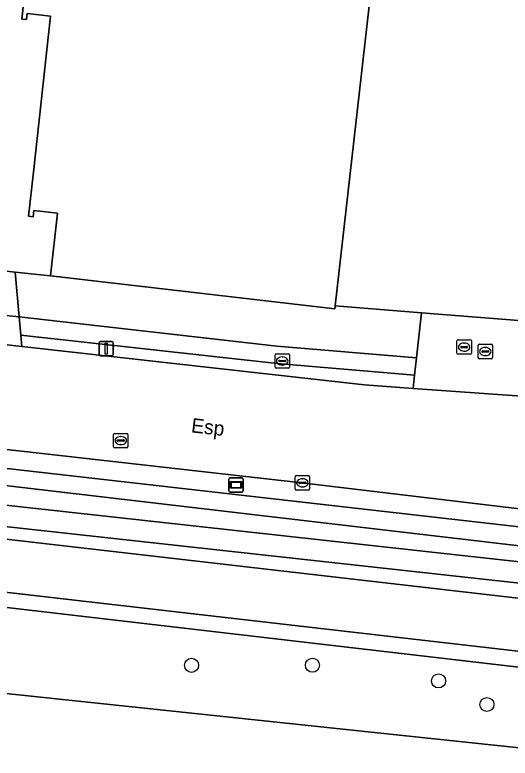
# Model space of a CAD drawing. Extents: x 161385 to 162589, y 388479 to 389756.
# Drawn here: x 162384.5 to 162418.9, y 388644.4 to 388696.1 of the extents above; entities that cross this region are included whole.
import ezdxf

# ---------------------------------------------------------------- set-up
doc = ezdxf.new("R2010")
doc.units = 0
for name, color, linetype in [('IMGEO_Berm_groen', 7, 'Continuous'), ('IMGEO_Boom', 7, 'Continuous'), ('IMGEO_Brandkraan', 7, 'Continuous'), ('IMGEO_Erf', 7, 'Continuous'), ('IMGEO_Fietspad_gesloten', 7, 'Continuous'), ('IMGEO_Gemengd_bos', 7, 'Continuous'), ('IMGEO_Groenvoorziening', 7, 'Continuous'), ('IMGEO_Haag', 7, 'Continuous'), ('IMGEO_Hek', 7, 'Continuous'), ('IMGEO_Kolk', 7, 'Continuous'), ('IMGEO_Lichtmast', 7, 'Continuous'), ('IMGEO_Oever', 7, 'Continuous'), ('IMGEO_Openbare_ruimte_label', 7, 'Continuous'), ('IMGEO_Pand', 7, 'Continuous'), ('IMGEO_Rijbaan_lokaal_gesloten', 7, 'Continuous'), ('IMGEO_Rioolput', 7, 'Continuous'), ('IMGEO_Voetpad_open', 7, 'Continuous'), ('IMGEO_Waterloop', 7, 'Continuous'), ('IMGEO_Wegwijzer', 7, 'Continuous')]:
    doc.layers.add(name, color=color, linetype=linetype)

msp = doc.modelspace()

# ---------------------------------------------------------------- linework, layer by layer
at = {"layer": 'IMGEO_Berm_groen'}
msp.add_lwpolyline([(162384.891, 388673.825), (162384.963, 388673.046), (162408.796, 388670.377), (162412.183, 388670.136), (162412.286, 388671.047), (162402.725, 388671.854)], close=True, dxfattribs=at)
for points in [[(162461.096, 388654.743), (162455.305, 388656.124), (162451.142, 388657.117), (162433.533, 388660.124), (162428.321, 388660.721), (162404.449, 388663.572), (162379.371, 388666.385), (162354.354, 388669.216), (162352.961, 388669.418), (162351.555, 388669.495), (162350.951, 388669.489), (162349.541, 388669.386), (162348.146, 388669.157), (162346.778, 388668.804), (162345.446, 388668.33), (162344.161, 388667.74), (162343.323, 388667.275), (162343.185, 388667.161), (162343.057, 388667.034), (162342.942, 388666.897), (162342.839, 388666.75), (162342.749, 388666.595), (162342.711, 388666.516)], [(162353.131, 388667.917), (162357.64, 388667.549), (162433.197, 388658.957), (162436.225, 388658.419), (162436.595, 388658.23), (162437.013, 388657.873), (162437.321, 388657.419), (162437.524, 388656.717), (162437.256, 388654.736)], [(162342.861, 388664.571), (162343.854, 388664.303), (162356.884, 388662.764), (162437.393, 388653.479), (162447.573, 388652.333)], [(162435.304, 388653.875), (162432.217, 388654.406), (162426.956, 388655.776), (162357.235, 388663.453), (162352.368, 388663.746)], [(162444.332, 388649.048), (162443.05, 388649.15), (162347.086, 388660.188)], [(162343.501, 388659.601), (162454.958, 388646.611)]]:
    msp.add_lwpolyline(points, dxfattribs=at)
at = {"layer": 'IMGEO_Boom'}
for centre in [(162396.77, 388650.877), (162405.18, 388650.883), (162413.953, 388649.79), (162417.32, 388648.153)]:
    msp.add_circle(centre, 0.489, dxfattribs=at)
at = {"layer": 'IMGEO_Brandkraan'}
for p, q in [((162402.653, 388672.538), (162403.505, 388672.538)), ((162402.578, 388671.612), (162402.578, 388672.464)), ((162402.837, 388672.032), (162402.837, 388672.044)), ((162403.275, 388671.995), (162402.877, 388671.995)), ((162402.88, 388672.081), (162403.278, 388672.081)), ((162403.066, 388672.318), (162403.091, 388672.318)), ((162403.321, 388672.044), (162403.321, 388672.032)), ((162403.579, 388672.464), (162403.579, 388671.612)), ((162403.505, 388671.538), (162402.653, 388671.538)), ((162403.089, 388671.758), (162403.064, 388671.758))]:
    msp.add_line(p, q, dxfattribs=at)
for points in [[(162402.653, 388672.538), (162403.505, 388672.538)], [(162402.578, 388671.612), (162402.578, 388672.464)], [(162403.579, 388672.464), (162403.579, 388671.612)], [(162403.505, 388671.538), (162402.653, 388671.538)]]:
    msp.add_lwpolyline(points, dxfattribs=at)
for centre, radius, start, end in [((162402.655, 388672.462), 0.0765, 91.552, 178.448), ((162402.655, 388672.462), 0.0765, 91.552, 178.448), ((162403.503, 388672.462), 0.0765, 1.552, 88.448), ((162403.503, 388672.462), 0.0765, 1.552, 88.448), ((162402.877, 388672.041), 0.0403, 85.8775, 175.7526), ((162402.874, 388672.031), 0.0366, 178.938, 274.7102), ((162403.278, 388672.038), 0.043, 264.8664, 352.4533), ((162403.282, 388672.043), 0.0386, 1.7309, 96.639), ((162402.655, 388671.614), 0.0765, 181.552, 268.448), ((162402.655, 388671.614), 0.0765, 181.552, 268.448), ((162403.503, 388671.614), 0.0765, 271.552, 358.448), ((162403.503, 388671.614), 0.0765, 271.552, 358.448)]:
    msp.add_arc(centre, radius, start, end, dxfattribs=at)
for centre, major_axis, ratio, start_param, end_param in [((162403.065, 388672.038), (-0.387, 0.002), 0.722429, 4.712389, 7.853982), ((162403.09, 388672.038), (-0.39, 0.002), 0.717154, 1.570796, 4.712389)]:
    msp.add_ellipse(centre, major_axis=major_axis, ratio=ratio, start_param=start_param, end_param=end_param, dxfattribs=at)
at = {"layer": 'IMGEO_Erf'}
for points in [[(162383.967, 388722.64), (162411.707, 388719.457), (162406.76, 388675.873), (162412.776, 388675.396), (162420.122, 388674.813), (162420.461, 388674.786), (162446.489, 388672.997), (162447.18, 388679), (162448.384, 388678.861), (162448.49, 388679.822), (162449.227, 388686.456), (162448.051, 388686.549), (162448.713, 388692.673), (162448.008, 388692.753), (162425.971, 388695.283), (162429.384, 388725.33), (162435.4, 388724.653), (162435.751, 388727.776), (162406.633, 388731.063), (162412.095, 388778.923)], [(162379.117, 388678.821), (162384.504, 388678.222), (162386.947, 388677.951), (162387.452, 388682.311), (162385.802, 388682.494), (162385.755, 388682.067), (162385.427, 388682.103), (162385.766, 388685.174), (162386.965, 388696.018), (162385.325, 388696.199), (162385.279, 388695.782), (162384.951, 388695.818), (162386.201, 388707.129), (162384.591, 388707.307), (162384.544, 388706.88), (162384.216, 388706.916), (162385.484, 388718.406), (162383.83, 388718.549)], [(162443.528, 388629.496), (162453.713, 388637.19), (162458.56, 388641.004), (162341.543, 388653.38), (162336.168, 388605.315)]]:
    msp.add_lwpolyline(points, dxfattribs=at)
at = {"layer": 'IMGEO_Fietspad_gesloten'}
for points in [[(162447.573, 388652.333), (162437.393, 388653.479), (162356.884, 388662.764)], [(162338.468, 388662.352), (162347.086, 388660.188), (162443.05, 388649.15), (162444.332, 388649.048)]]:
    msp.add_lwpolyline(points, dxfattribs=at)
at = {"layer": 'IMGEO_Gemengd_bos'}
msp.add_lwpolyline([(162341.994, 388657.41), (162341.543, 388653.38), (162458.56, 388641.004), (162459.614, 388641.987), (162460.571, 388643.599), (162460.446, 388643.694), (162457.403, 388645.374), (162454.958, 388646.611), (162343.501, 388659.601)], dxfattribs=at)
at = {"layer": 'IMGEO_Groenvoorziening'}
msp.add_lwpolyline([(162384.504, 388678.222), (162384.771, 388675.111), (162402.707, 388673.075), (162412.421, 388672.249), (162412.776, 388675.396), (162406.76, 388675.873), (162406.736, 388675.658), (162386.947, 388677.951)], close=True, dxfattribs=at)
at = {"layer": 'IMGEO_Haag'}
msp.add_lwpolyline([(162384.504, 388678.222), (162384.771, 388675.111), (162402.707, 388673.075), (162412.421, 388672.249), (162412.776, 388675.396), (162406.76, 388675.873), (162406.736, 388675.658), (162386.947, 388677.951)], close=True, dxfattribs=at)
at = {"layer": 'IMGEO_Hek'}
for points in [[(162412.776, 388675.396), (162406.76, 388675.873)], [(162420.122, 388674.813), (162412.776, 388675.396)]]:
    msp.add_lwpolyline(points, dxfattribs=at)
at = {"layer": 'IMGEO_Kolk'}
for p, q in [((162403.981, 388663.141), (162403.981, 388663.993)), ((162404.056, 388664.067), (162404.908, 388664.067)), ((162404.469, 388663.847), (162404.494, 388663.847)), ((162404.982, 388663.993), (162404.982, 388663.141)), ((162404.24, 388663.561), (162404.24, 388663.573)), ((162404.678, 388663.524), (162404.28, 388663.524)), ((162404.283, 388663.61), (162404.681, 388663.61)), ((162404.492, 388663.287), (162404.467, 388663.287)), ((162404.724, 388663.573), (162404.724, 388663.561)), ((162404.908, 388663.067), (162404.056, 388663.067))]:
    msp.add_line(p, q, dxfattribs=at)
for points in [[(162403.981, 388663.141), (162403.981, 388663.993)], [(162404.056, 388664.067), (162404.908, 388664.067)], [(162404.982, 388663.993), (162404.982, 388663.141)], [(162404.908, 388663.067), (162404.056, 388663.067)]]:
    msp.add_lwpolyline(points, dxfattribs=at)
for centre, radius, start, end in [((162404.058, 388663.991), 0.0765, 91.552, 178.448), ((162404.058, 388663.991), 0.0765, 91.552, 178.448), ((162404.906, 388663.991), 0.0765, 1.552, 88.448), ((162404.906, 388663.991), 0.0765, 1.552, 88.448), ((162404.28, 388663.57), 0.0403, 85.8775, 175.7526), ((162404.277, 388663.56), 0.0366, 178.938, 274.7102), ((162404.681, 388663.567), 0.043, 264.8664, 352.4533), ((162404.685, 388663.572), 0.0386, 1.7309, 96.639), ((162404.058, 388663.143), 0.0765, 181.552, 268.448), ((162404.058, 388663.143), 0.0765, 181.552, 268.448), ((162404.906, 388663.143), 0.0765, 271.552, 358.448), ((162404.906, 388663.143), 0.0765, 271.552, 358.448)]:
    msp.add_arc(centre, radius, start, end, dxfattribs=at)
for centre, major_axis, ratio, start_param, end_param in [((162404.468, 388663.567), (-0.387, 0.002), 0.722429, 4.712389, 7.853982), ((162404.493, 388663.567), (-0.39, 0.002), 0.717154, 1.570796, 4.712389)]:
    msp.add_ellipse(centre, major_axis=major_axis, ratio=ratio, start_param=start_param, end_param=end_param, dxfattribs=at)
at = {"layer": 'IMGEO_Lichtmast'}
for p, q in [((162390.335, 388672.501), (162390.335, 388673.301)), ((162390.335, 388673.301), (162390.335, 388672.501)), ((162390.435, 388673.401), (162391.225, 388673.401)), ((162391.225, 388673.401), (162390.435, 388673.401)), ((162391.325, 388673.301), (162391.325, 388672.501)), ((162391.325, 388672.501), (162391.325, 388673.301)), ((162391.225, 388672.401), (162390.435, 388672.401)), ((162390.435, 388672.401), (162391.225, 388672.401))]:
    msp.add_line(p, q, dxfattribs=at)
msp.add_lwpolyline([(162390.755, 388673.276), (162390.905, 388673.276), (162390.905, 388672.526), (162390.755, 388672.526), (162390.755, 388673.276)], dxfattribs=at)
for centre, start, end in [((162390.435, 388673.301), 90, 180), ((162390.435, 388673.301), 90, 180), ((162391.225, 388673.301), 0, 90), ((162391.225, 388673.301), 360, 90), ((162390.435, 388672.501), 180, 270), ((162390.435, 388672.501), 180, 270), ((162391.225, 388672.501), 270, 0), ((162391.225, 388672.501), 270, 0)]:
    msp.add_arc(centre, 0.1, start, end, dxfattribs=at)
at = {"layer": 'IMGEO_Oever'}
for points in [[(162437.256, 388654.736), (162437.524, 388656.717), (162437.321, 388657.419), (162437.013, 388657.873), (162436.595, 388658.23), (162436.225, 388658.419), (162433.197, 388658.957), (162357.64, 388667.549)], [(162352.987, 388666.821), (162353.241, 388666.814), (162357.696, 388666.45), (162433.015, 388657.61), (162435.457, 388657.224)], [(162435.326, 388655.82), (162435.12, 388655.826), (162427.37, 388657.224), (162357.525, 388664.915), (162352.705, 388665.205)], [(162352.368, 388663.746), (162357.235, 388663.453), (162426.956, 388655.776), (162432.217, 388654.406), (162435.304, 388653.875)]]:
    msp.add_lwpolyline(points, dxfattribs=at)
at = {"layer": 'IMGEO_Pand'}
msp.add_lwpolyline([(162411.707, 388719.457), (162383.967, 388722.64), (162383.521, 388718.755), (162383.498, 388718.557), (162383.453, 388718.159), (162383.781, 388718.121), (162383.83, 388718.549), (162385.484, 388718.406), (162384.216, 388706.916), (162384.544, 388706.88), (162384.591, 388707.307), (162386.201, 388707.129), (162384.951, 388695.818), (162385.279, 388695.782), (162385.325, 388696.199), (162386.965, 388696.018), (162385.766, 388685.174), (162385.427, 388682.103), (162385.755, 388682.067), (162385.802, 388682.494), (162387.452, 388682.311), (162386.947, 388677.951), (162406.736, 388675.658), (162406.76, 388675.873)], close=True, dxfattribs=at)
at = {"layer": 'IMGEO_Rijbaan_lokaal_gesloten'}
for points in [[(162384.963, 388673.046), (162379.189, 388673.693), (162354.148, 388676.497), (162353.423, 388676.578), (162317.536, 388680.643)], [(162465.876, 388665.019), (162452.648, 388667.218), (162447.672, 388667.734), (162437.734, 388668.476), (162428.744, 388668.955), (162419.72, 388669.598), (162412.183, 388670.136), (162408.796, 388670.377), (162384.963, 388673.046)], [(162320.835, 388672.971), (162352.961, 388669.418), (162354.354, 388669.216), (162379.371, 388666.385), (162404.449, 388663.572), (162428.321, 388660.721), (162433.533, 388660.124), (162451.142, 388657.117), (162455.305, 388656.124), (162461.096, 388654.743), (162466.578, 388653.381)]]:
    msp.add_lwpolyline(points, dxfattribs=at)
at = {"layer": 'IMGEO_Rioolput'}
for p, q in [((162415.236, 388672.579), (162415.236, 388673.431)), ((162415.311, 388673.505), (162416.163, 388673.505)), ((162415.495, 388672.999), (162415.495, 388673.011)), ((162415.538, 388673.048), (162415.936, 388673.048)), ((162415.724, 388673.285), (162415.749, 388673.285)), ((162415.979, 388673.011), (162415.979, 388672.999)), ((162416.237, 388673.431), (162416.237, 388672.579)), ((162416.703, 388672.273), (162416.703, 388673.125)), ((162416.778, 388673.199), (162417.63, 388673.199)), ((162417.704, 388673.125), (162417.704, 388672.273)), ((162416.163, 388672.505), (162415.311, 388672.505)), ((162415.933, 388672.962), (162415.535, 388672.962)), ((162415.747, 388672.725), (162415.722, 388672.725)), ((162416.962, 388672.693), (162416.962, 388672.705)), ((162417.4, 388672.656), (162417.002, 388672.656)), ((162417.005, 388672.742), (162417.403, 388672.742)), ((162417.191, 388672.979), (162417.216, 388672.979)), ((162417.446, 388672.705), (162417.446, 388672.693)), ((162417.63, 388672.199), (162416.778, 388672.199)), ((162417.214, 388672.419), (162417.189, 388672.419)), ((162391.346, 388666.078), (162391.346, 388666.93)), ((162391.421, 388667.004), (162392.273, 388667.004)), ((162392.347, 388666.93), (162392.347, 388666.078)), ((162391.605, 388666.498), (162391.605, 388666.51)), ((162392.043, 388666.461), (162391.645, 388666.461)), ((162391.648, 388666.547), (162392.046, 388666.547)), ((162391.834, 388666.784), (162391.859, 388666.784)), ((162392.089, 388666.51), (162392.089, 388666.498)), ((162392.273, 388666.004), (162391.421, 388666.004)), ((162391.857, 388666.224), (162391.832, 388666.224))]:
    msp.add_line(p, q, dxfattribs=at)
for points in [[(162415.236, 388672.579), (162415.236, 388673.431)], [(162415.311, 388673.505), (162416.163, 388673.505)], [(162416.237, 388673.431), (162416.237, 388672.579)], [(162416.703, 388672.273), (162416.703, 388673.125)], [(162416.778, 388673.199), (162417.63, 388673.199)], [(162417.704, 388673.125), (162417.704, 388672.273)], [(162416.163, 388672.505), (162415.311, 388672.505)], [(162417.63, 388672.199), (162416.778, 388672.199)], [(162391.346, 388666.078), (162391.346, 388666.93)], [(162391.421, 388667.004), (162392.273, 388667.004)], [(162392.347, 388666.93), (162392.347, 388666.078)], [(162392.273, 388666.004), (162391.421, 388666.004)]]:
    msp.add_lwpolyline(points, dxfattribs=at)
for centre, radius, start, end in [((162415.313, 388673.429), 0.0765, 91.552, 178.448), ((162415.313, 388673.429), 0.0765, 91.552, 178.448), ((162415.535, 388673.008), 0.0403, 85.8775, 175.7526), ((162415.532, 388672.998), 0.0366, 178.938, 274.7102), ((162415.936, 388673.005), 0.043, 264.8664, 352.4533), ((162415.94, 388673.01), 0.0386, 1.7309, 96.639), ((162416.161, 388673.429), 0.0765, 1.552, 88.448), ((162416.161, 388673.429), 0.0765, 1.552, 88.448), ((162416.78, 388673.123), 0.0765, 91.552, 178.448), ((162416.78, 388673.123), 0.0765, 91.552, 178.448), ((162417.628, 388673.123), 0.0765, 1.552, 88.448), ((162417.628, 388673.123), 0.0765, 1.552, 88.448), ((162415.313, 388672.581), 0.0765, 181.552, 268.448), ((162415.313, 388672.581), 0.0765, 181.552, 268.448), ((162416.161, 388672.581), 0.0765, 271.552, 358.448), ((162416.161, 388672.581), 0.0765, 271.552, 358.448), ((162417.002, 388672.702), 0.0403, 85.8775, 175.7526), ((162416.999, 388672.692), 0.0366, 178.938, 274.7102), ((162417.403, 388672.699), 0.043, 264.8664, 352.4533), ((162417.407, 388672.704), 0.0386, 1.7309, 96.639), ((162416.78, 388672.275), 0.0765, 181.552, 268.448), ((162416.78, 388672.275), 0.0765, 181.552, 268.448), ((162417.628, 388672.275), 0.0765, 271.552, 358.448), ((162417.628, 388672.275), 0.0765, 271.552, 358.448), ((162391.423, 388666.928), 0.0765, 91.552, 178.448), ((162391.423, 388666.928), 0.0765, 91.552, 178.448), ((162392.271, 388666.928), 0.0765, 1.552, 88.448), ((162392.271, 388666.928), 0.0765, 1.552, 88.448), ((162391.645, 388666.507), 0.0403, 85.8775, 175.7526), ((162391.642, 388666.497), 0.0366, 178.938, 274.7102), ((162392.046, 388666.504), 0.043, 264.8664, 352.4533), ((162392.05, 388666.509), 0.0386, 1.7309, 96.639), ((162391.423, 388666.08), 0.0765, 181.552, 268.448), ((162391.423, 388666.08), 0.0765, 181.552, 268.448), ((162392.271, 388666.08), 0.0765, 271.552, 358.448), ((162392.271, 388666.08), 0.0765, 271.552, 358.448)]:
    msp.add_arc(centre, radius, start, end, dxfattribs=at)
for centre, major_axis, ratio, start_param, end_param in [((162415.723, 388673.005), (-0.387, 0.002), 0.722429, 4.712389, 7.853982), ((162415.748, 388673.005), (-0.39, 0.002), 0.717154, 1.570796, 4.712389), ((162417.19, 388672.699), (-0.387, 0.002), 0.722429, 4.712389, 7.853982), ((162417.215, 388672.699), (-0.39, 0.002), 0.717154, 1.570796, 4.712389), ((162391.833, 388666.504), (-0.387, 0.002), 0.722429, 4.712389, 7.853982), ((162391.858, 388666.504), (-0.39, 0.002), 0.717154, 1.570796, 4.712389)]:
    msp.add_ellipse(centre, major_axis=major_axis, ratio=ratio, start_param=start_param, end_param=end_param, dxfattribs=at)
at = {"layer": 'IMGEO_Voetpad_open'}
for points in [[(162384.771, 388675.111), (162384.504, 388678.222), (162379.117, 388678.821), (162379.154, 388675.665)], [(162379.154, 388675.665), (162379.185, 388674.452), (162379.189, 388673.693), (162384.963, 388673.046), (162384.891, 388673.825), (162384.771, 388675.111)], [(162412.421, 388672.249), (162402.707, 388673.075), (162384.771, 388675.111), (162384.891, 388673.825), (162402.725, 388671.854), (162412.286, 388671.047)], [(162419.785, 388671.507), (162419.797, 388671.622), (162420.122, 388674.813), (162412.776, 388675.396), (162412.421, 388672.249), (162412.286, 388671.047), (162412.183, 388670.136), (162419.72, 388669.598), (162419.748, 388670.416)]]:
    msp.add_lwpolyline(points, close=True, dxfattribs=at)
at = {"layer": 'IMGEO_Waterloop'}
for points in [[(162436.21, 388656.379), (162436.185, 388656.773), (162436.144, 388656.871), (162435.992, 388657.07), (162435.866, 388657.143), (162435.67, 388657.197), (162435.457, 388657.224), (162433.015, 388657.61), (162357.696, 388666.45), (162353.241, 388666.814), (162352.987, 388666.821)], [(162352.705, 388665.205), (162357.525, 388664.915), (162427.37, 388657.224), (162435.12, 388655.826), (162435.326, 388655.82)]]:
    msp.add_lwpolyline(points, dxfattribs=at)
at = {"layer": 'IMGEO_Wegwijzer'}
for p, q in [((162399.367, 388663.017), (162399.367, 388663.817)), ((162399.367, 388663.817), (162399.367, 388663.017)), ((162399.467, 388663.917), (162400.257, 388663.917)), ((162400.257, 388663.917), (162399.467, 388663.917)), ((162400.357, 388663.817), (162400.357, 388663.017)), ((162400.357, 388663.017), (162400.357, 388663.817)), ((162400.257, 388662.917), (162399.467, 388662.917)), ((162399.467, 388662.917), (162400.257, 388662.917))]:
    msp.add_line(p, q, dxfattribs=at)
for points in [[(162399.468, 388663.649), (162400.256, 388663.649), (162400.256, 388663.185), (162399.468, 388663.185), (162399.468, 388663.649)], [(162399.533, 388663.584), (162399.533, 388663.25), (162400.191, 388663.25), (162400.191, 388663.584), (162399.533, 388663.584)]]:
    msp.add_lwpolyline(points, dxfattribs=at)
for centre, start, end in [((162399.467, 388663.817), 90, 180), ((162399.467, 388663.817), 90, 180), ((162400.257, 388663.817), 0, 90), ((162400.257, 388663.817), 360, 90), ((162399.467, 388663.017), 180, 270), ((162399.467, 388663.017), 180, 270), ((162400.257, 388663.017), 270, 0), ((162400.257, 388663.017), 270, 0)]:
    msp.add_arc(centre, 0.1, start, end, dxfattribs=at)

# ---------------------------------------------------------------- texts
at = {"layer": 'IMGEO_Openbare_ruimte_label'}
msp.add_text('Esp', height=1, rotation=353.5143, dxfattribs=at).set_placement((162396.71, 388667.082))

doc.saveas('drawing.dxf')
